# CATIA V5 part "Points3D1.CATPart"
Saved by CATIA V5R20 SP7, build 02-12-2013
Part number: Part2
Bounding box of the stored display mesh (mm): x -100 to 749.738, y -565.212 to 100, z -149.943 to 300.194
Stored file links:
  C:\Users\CAS-\Downloads\Points3D1.CATPart
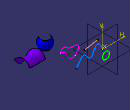
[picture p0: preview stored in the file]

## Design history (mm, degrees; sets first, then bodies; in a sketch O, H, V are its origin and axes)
Set1
  Point1: (0, 0, 0)
  Point2: (20, 0, 50)
  Point3: (70, 0, 100)
  Point4: (120, 0, 50)
  Point5: (170, 20, -20)
  Point6: (220, 40, 20)
  Point7: (270, 60, 60)
  Point8: (320, 80, 20)
  Point9: (370, 100, -50)
  Curve1: Elements (Point1; Point2; Point3; Point4; Point5; Point6; Point7; Point8; Point9)
  Point10: (70, 0, 150)
  Point11 "Point.11": (250, 0, 120)
  Line1: type PtPt, FirstPoint Point10, SecondPoint Point11
  Point12: (-50, 0, -100)
  Circle1: type CtrRad, Start 0, End 180, Center Point12, Support zx-plane, Radius 50
  Point13: (70, 100, 120)
  DatumSurface1
  Project1: ToProject Curve1, Support zx-plane
  Sketch1 on zx-plane, origin (0, 0, 0), H (-1, 0, 0), V (0, 0, 1)
    spline S1 through (-600, 250) (-550, 300) (-460, 250) (-350, 230) (-390, 120) (-490, 150) (-520, 210) (-600, 250)
    point P1 (-600, 250)
    point P2 (-600, 250)
    coincidence: P1 P2
  Point14: type OnCurve, Support Sketch1, RefPoint {extremum Reference Sketch1, Direction (1, 2, 3)}, Length 193.881
  Sphere1: Center {point type OnPlane, Support xy-plane, H 319.182, V -496.268, Direction (1, 0, 0)}, Radius 90, Angle1 -45, Angle3 -50, Angle4 180
Body1 (main body)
